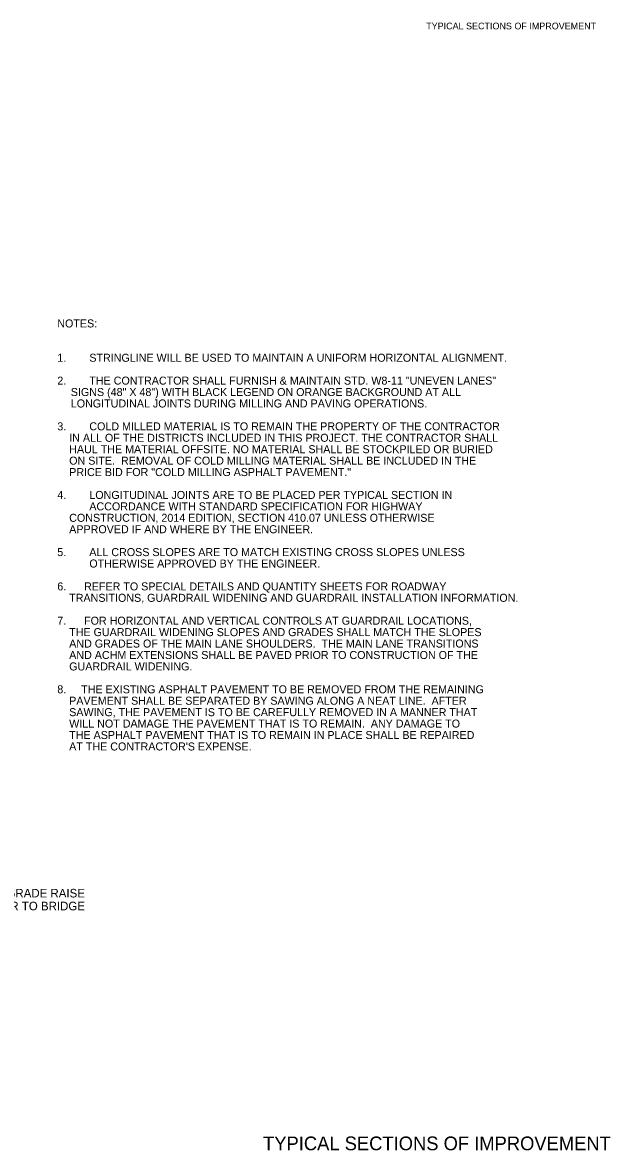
# Model space of a CAD drawing. Extents: x 544259 to 1930787, y -1961343 to 596640.
# Drawn here: x 545254 to 545768, y -1957443 to -1956456 of the extents above; entities that cross this region are included whole.
import ezdxf

# ---------------------------------------------------------------- set-up
doc = ezdxf.new("R2010")
doc.units = 0
for name, color, linetype in [('R_Border', 7, 'Continuous'), ('R_Border Notes', 7, 'Continuous'), ('R_Border Prem', 7, 'Continuous'), ('R_Draft', 7, 'Continuous')]:
    doc.layers.add(name, color=color, linetype=linetype)

msp = doc.modelspace()

# ---------------------------------------------------------------- texts
at = {"layer": 'R_Border'}
msp.add_text('TYPICAL SECTIONS OF IMPROVEMENT', height=12, rotation=360, dxfattribs=at).set_placement((545464.19, -1957442.8))
at = {"layer": 'R_Border Notes'}
for s, p in [('NOTES: ', (545284.31, -1956723.11)), ('1.', (545284.31, -1956753.11)), ('STRINGLINE WILL BE USED TO MAINTAIN A UNIFORM HORIZONTAL ALIGNMENT.', (545312.31, -1956753.11)), ('2.', (545284.31, -1956773.11)), ('THE CONTRACTOR SHALL FURNISH & MAINTAIN STD. W8-11 "UNEVEN LANES" ', (545312.31, -1956773.11)), ('    SIGNS (48" X 48") WITH BLACK LEGEND ON ORANGE BACKGROUND AT ALL ', (545285.71, -1956783.11)), ('    LONGITUDINAL JOINTS DURING MILLING AND PAVING OPERATIONS.', (545285.71, -1956793.11)), ('3.', (545284.31, -1956813.11)), ('COLD MILLED MATERIAL IS TO REMAIN THE PROPERTY OF THE CONTRACTOR', (545312.31, -1956813.11)), ('    IN ALL OF THE DISTRICTS INCLUDED IN THIS PROJECT. THE CONTRACTOR SHALL', (545284.31, -1956823.11)), ('    HAUL THE MATERIAL OFFSITE. NO MATERIAL SHALL BE STOCKPILED OR BURIED', (545284.31, -1956833.11)), ('    ON SITE.  REMOVAL OF COLD MILLING MATERIAL SHALL BE INCLUDED IN THE', (545284.31, -1956843.11)), ('    PRICE BID FOR "COLD MILLING ASPHALT PAVEMENT."', (545284.31, -1956853.11)), ('4.', (545284.31, -1956873.11)), ('LONGITUDINAL JOINTS ARE TO BE PLACED PER TYPICAL SECTION IN ', (545312.31, -1956873.11)), ('ACCORDANCE WITH STANDARD SPECIFICATION FOR HIGHWAY', (545312.31, -1956883.11)), ('    CONSTRUCTION, 2014 EDITION, SECTION 410.07 UNLESS OTHERWISE', (545284.31, -1956893.11)), ('    APPROVED IF AND WHERE BY THE ENGINEER.', (545284.31, -1956903.11)), ('5.', (545284.31, -1956923.11)), ('ALL CROSS SLOPES ARE TO MATCH EXISTING CROSS SLOPES UNLESS ', (545312.31, -1956923.11)), ('OTHERWISE APPROVED BY THE ENGINEER.', (545312.31, -1956933.11)), ('6.      REFER TO SPECIAL DETAILS AND QUANTITY SHEETS FOR ROADWAY', (545284.31, -1956953.11)), ('    TRANSITIONS, GUARDRAIL WIDENING AND GUARDRAIL INSTALLATION INFORMATION.', (545284.31, -1956963.11)), ('7.      FOR HORIZONTAL AND VERTICAL CONTROLS AT GUARDRAIL LOCATIONS,', (545284.31, -1956983.11)), ('    THE GUARDRAIL WIDENING SLOPES AND GRADES SHALL MATCH THE SLOPES', (545284.31, -1956993.11)), ('    AND GRADES OF THE MAIN LANE SHOULDERS.  THE MAIN LANE TRANSITIONS', (545284.31, -1957003.11)), ('    AND ACHM EXTENSIONS SHALL BE PAVED PRIOR TO CONSTRUCTION OF THE', (545284.31, -1957013.11)), ('    GUARDRAIL WIDENING.', (545284.31, -1957023.11)), ('8.     THE EXISTING ASPHALT PAVEMENT TO BE REMOVED FROM THE REMAINING', (545284.31, -1957043.11)), ('    PAVEMENT SHALL BE SEPARATED BY SAWING ALONG A NEAT LINE.  AFTER', (545284.31, -1957053.11)), ('    SAWING, THE PAVEMENT IS TO BE CAREFULLY REMOVED IN A MANNER THAT ', (545284.31, -1957063.11)), ('    WILL NOT DAMAGE THE PAVEMENT THAT IS TO REMAIN.  ANY DAMAGE TO', (545284.31, -1957073.11)), ('    THE ASPHALT PAVEMENT THAT IS TO REMAIN IN PLACE SHALL BE REPAIRED', (545284.31, -1957083.11)), ("    AT THE CONTRACTOR'S EXPENSE.", (545284.31, -1957093.11))]:
    msp.add_text(s, height=7, dxfattribs=at).set_placement(p)
at = {"layer": 'R_Border Prem'}
msp.add_text('TYPICAL SECTIONS OF IMPROVEMENT', height=5.862, rotation=360, dxfattribs=at).set_placement((545606.81, -1956462.38))
at = {"layer": 'R_Draft'}
for s, p in [('NOTE: BRIDGE M3479 WILL HAVE A 1" GRADE RAISE', (545054.07, -1957221.69)), ('       WITH FINISHED RESURFACING.  REFER TO BRIDGE', (545037.68, -1957232.94))]:
    msp.add_text(s, height=7.5, dxfattribs=at).set_placement(p)

doc.saveas('drawing.dxf')
